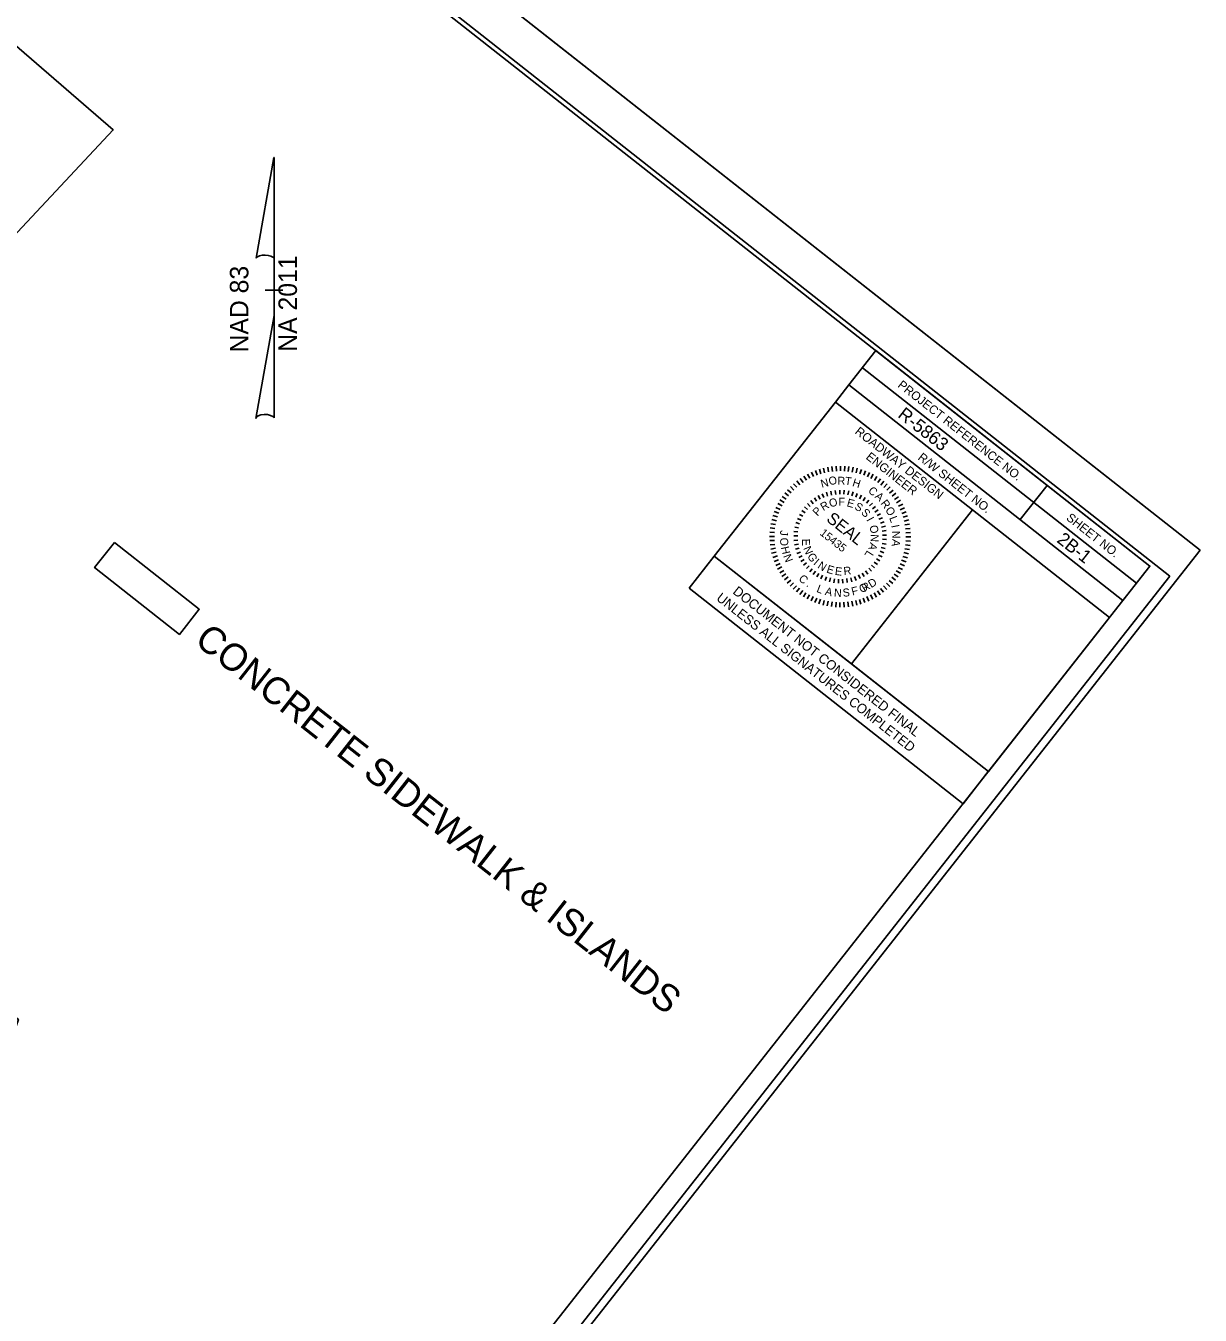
# Model space of a CAD drawing. Extents: x 556999 to 558602, y 505955 to 507732.
# Drawn here: x 558063 to 558602, y 506548 to 507140 of the extents above; entities that cross this region are included whole.
import ezdxf

# ---------------------------------------------------------------- set-up
doc = ezdxf.new("R2010")
doc.units = 0
for name, color, linetype in [('Old_Level_21', 7, 'Continuous'), ('Prop Conc 4in Sidewalk', 7, 'Continuous'), ('Prop Dimension', 7, 'Continuous'), ('Prop Horizontal Alignment Station Label', 7, 'Continuous'), ('Sheet Border Standard 30in CELL', 7, 'Continuous'), ('Sheet Clip Boundary CELL', 7, 'Continuous'), ('Sheet Cutting Line CELL', 7, 'Continuous'), ('Sheet Data Field CELL', 7, 'Continuous'), ('Sheet Plot Border Inside CELL', 7, 'Continuous'), ('Sheet Plot Border Outside CELL', 7, 'Continuous'), ('Sheet Sticker Exception Certification CELL', 7, 'Continuous')]:
    doc.layers.add(name, color=color, linetype=linetype)

msp = doc.modelspace()

# ---------------------------------------------------------------- linework, layer by layer
at = {"layer": 'Old_Level_21'}
for p, q in [((558420.11, 506932.76), (558421.25, 506930.86)), ((558421.82, 506933.71), (558422.84, 506931.76)), ((558423.58, 506934.57), (558424.48, 506932.55)), ((558425.39, 506935.31), (558426.17, 506933.24)), ((558427.24, 506935.94), (558427.89, 506933.83)), ((558429.13, 506936.46), (558429.65, 506934.32)), ((558431.04, 506936.86), (558431.43, 506934.69)), ((558432.98, 506937.15), (558433.24, 506934.96)), ((558434.92, 506937.32), (558435.05, 506935.12)), ((558436.88, 506937.37), (558436.87, 506935.17)), ((558438.84, 506937.31), (558438.7, 506935.11)), ((558440.78, 506937.13), (558440.51, 506934.94)), ((558442.72, 506936.83), (558442.31, 506934.66)), ((558444.63, 506936.41), (558444.09, 506934.27)), ((558446.51, 506935.88), (558445.85, 506933.77)), ((558448.36, 506935.24), (558447.57, 506933.17)), ((558450.16, 506934.48), (558449.25, 506932.47)), ((558451.92, 506933.62), (558450.89, 506931.67)), ((558453.62, 506932.65), (558452.47, 506930.77)), ((558413.95, 506927.96), (558415.51, 506926.4)), ((558415.38, 506929.3), (558416.84, 506927.65)), ((558416.89, 506930.55), (558418.24, 506928.81)), ((558418.47, 506931.71), (558419.72, 506929.88)), ((558455.26, 506931.58), (558454, 506929.77)), ((558456.83, 506930.42), (558455.46, 506928.69)), ((558458.33, 506929.16), (558456.86, 506927.51)), ((558459.75, 506927.82), (558458.19, 506926.26)), ((558409.12, 506921.83), (558411, 506920.69)), ((558410.19, 506923.47), (558412, 506922.21)), ((558411.35, 506925.05), (558413.08, 506923.68)), ((558412.61, 506926.54), (558414.26, 506925.08)), ((558423.27, 506921.51), (558424.43, 506920.09)), ((558424.92, 506922.74), (558425.95, 506921.21)), ((558426.69, 506923.8), (558427.56, 506922.18)), ((558428.56, 506924.69), (558429.26, 506922.99)), ((558430.49, 506925.39), (558431.03, 506923.63)), ((558432.49, 506925.9), (558432.86, 506924.1)), ((558434.53, 506926.22), (558434.72, 506924.38)), ((558436.59, 506926.34), (558436.6, 506924.49)), ((558438.65, 506926.25), (558438.48, 506924.42)), ((558440.69, 506925.97), (558440.35, 506924.17)), ((558442.7, 506925.5), (558442.19, 506923.73)), ((558444.65, 506924.83), (558443.97, 506923.12)), ((558446.53, 506923.98), (558445.69, 506922.34)), ((558448.31, 506922.95), (558447.32, 506921.4)), ((558449.99, 506921.75), (558448.86, 506920.31)), ((558448.86, 506920.31), (558449.99, 506921.75)), ((558461.09, 506926.39), (558459.43, 506924.93)), ((558462.33, 506924.88), (558460.59, 506923.53)), ((558463.49, 506923.3), (558461.67, 506922.05)), ((558464.54, 506921.66), (558462.65, 506920.52)), ((558406.53, 506916.57), (558408.6, 506915.78)), ((558407.29, 506918.38), (558409.3, 506917.46)), ((558408.15, 506920.13), (558410.1, 506919.1)), ((558418.03, 506915.2), (558419.65, 506914.32)), ((558419.1, 506916.96), (558420.63, 506915.93)), ((558420.34, 506918.61), (558421.76, 506917.44)), ((558421.73, 506920.13), (558423.03, 506918.83)), ((558451.55, 506920.39), (558450.28, 506919.07)), ((558452.97, 506918.9), (558451.57, 506917.7)), ((558454.23, 506917.27), (558452.73, 506916.21)), ((558455.34, 506915.53), (558453.74, 506914.62)), ((558465.5, 506919.95), (558463.54, 506918.93)), ((558466.35, 506918.19), (558464.33, 506917.29)), ((558467.09, 506916.38), (558465.03, 506915.6)), ((558404.64, 506909), (558406.83, 506908.73)), ((558404.94, 506910.93), (558407.11, 506910.53)), ((558405.36, 506912.84), (558407.5, 506912.31)), ((558405.89, 506914.73), (558408, 506914.06)), ((558415.9, 506909.41), (558417.7, 506909.03)), ((558416.42, 506911.41), (558418.17, 506910.85)), ((558417.13, 506913.34), (558418.82, 506912.62)), ((558456.27, 506913.69), (558454.59, 506912.94)), ((558457.02, 506911.77), (558455.27, 506911.18)), ((558457.58, 506909.78), (558455.78, 506909.37)), ((558467.73, 506914.53), (558465.62, 506913.88)), ((558468.24, 506912.64), (558466.1, 506912.12)), ((558468.65, 506910.73), (558466.48, 506910.34)), ((558404.39, 506905.1), (558406.6, 506905.09)), ((558404.45, 506903.14), (558406.65, 506903.27)), ((558404.46, 506907.05), (558406.66, 506906.91)), ((558415.43, 506905.32), (558417.28, 506905.29)), ((558415.51, 506903.26), (558417.34, 506903.41)), ((558415.57, 506907.38), (558417.39, 506907.17)), ((558457.94, 506907.75), (558456.11, 506907.51)), ((558458.08, 506903.64), (558456.24, 506903.75)), ((558458.11, 506905.7), (558456.27, 506905.64)), ((558468.94, 506908.79), (558466.74, 506908.53)), ((558469.09, 506902.93), (558466.89, 506903.07)), ((558469.11, 506906.84), (558466.9, 506906.72)), ((558469.16, 506904.89), (558466.95, 506904.89)), ((558404.62, 506901.19), (558406.81, 506901.45)), ((558404.91, 506899.26), (558407.08, 506899.65)), ((558405.31, 506897.34), (558407.45, 506897.86)), ((558415.77, 506901.21), (558417.58, 506901.54)), ((558416.23, 506899.2), (558418, 506899.7)), ((558416.89, 506897.25), (558418.6, 506897.92)), ((558456.8, 506897.6), (558455.07, 506898.24)), ((558457.42, 506899.57), (558455.64, 506900.03)), ((558457.85, 506901.59), (558456.03, 506901.88)), ((558468.19, 506897.14), (558466.05, 506897.68)), ((558468.61, 506899.05), (558466.44, 506899.46)), ((558468.91, 506900.99), (558466.72, 506901.26)), ((558405.83, 506895.46), (558407.94, 506896.11)), ((558406.46, 506893.61), (558408.53, 506894.38)), ((558407.2, 506891.8), (558409.22, 506892.7)), ((558417.73, 506895.36), (558419.37, 506896.19)), ((558418.75, 506893.57), (558420.3, 506894.55)), ((558421.38, 506893.02), (558419.92, 506891.89)), ((558421.28, 506890.32), (558422.61, 506891.58)), ((558452.53, 506890.6), (558451.18, 506891.83)), ((558453.85, 506892.18), (558452.38, 506893.29)), ((558455.01, 506893.89), (558453.44, 506894.85)), ((558455.99, 506895.7), (558454.34, 506896.5)), ((558466.26, 506891.6), (558464.26, 506892.52)), ((558467.02, 506893.41), (558464.96, 506894.2)), ((558467.66, 506895.26), (558465.56, 506895.92)), ((558408.06, 506890.04), (558410.01, 506891.06)), ((558409.01, 506888.33), (558410.9, 506889.46)), ((558410.06, 506886.68), (558411.89, 506887.93)), ((558411.22, 506885.1), (558412.96, 506886.46)), ((558422.77, 506888.89), (558423.97, 506890.28)), ((558424.38, 506887.61), (558425.45, 506889.11)), ((558426.12, 506886.5), (558427.04, 506888.09)), ((558427.95, 506885.56), (558428.71, 506887.24)), ((558429.87, 506884.8), (558430.47, 506886.54)), ((558431.85, 506884.23), (558432.28, 506886.02)), ((558433.88, 506883.85), (558434.13, 506885.67)), ((558435.94, 506883.67), (558436.01, 506885.5)), ((558438, 506883.68), (558437.89, 506885.52)), ((558440.05, 506883.9), (558439.77, 506885.72)), ((558442.07, 506884.31), (558441.61, 506886.1)), ((558444.04, 506884.92), (558443.41, 506886.65)), ((558445.94, 506885.72), (558445.15, 506887.38)), ((558447.76, 506886.69), (558446.81, 506888.27)), ((558449.47, 506887.83), (558448.38, 506889.31)), ((558449.89, 506890.55), (558451.12, 506889.19)), ((558462.2, 506884.94), (558460.47, 506886.31)), ((558463.37, 506886.51), (558461.56, 506887.77)), ((558464.43, 506888.15), (558462.55, 506889.3)), ((558465.4, 506889.85), (558463.45, 506890.88)), ((558412.47, 506883.6), (558414.12, 506885.05)), ((558413.81, 506882.17), (558415.37, 506883.72)), ((558415.22, 506880.82), (558416.69, 506882.47)), ((558416.72, 506879.57), (558418.09, 506881.3)), ((558418.3, 506878.4), (558419.56, 506880.21)), ((558455.09, 506878.28), (558453.84, 506880.1)), ((558456.67, 506879.44), (558455.31, 506881.18)), ((558458.17, 506880.68), (558456.72, 506882.34)), ((558459.6, 506882.02), (558458.05, 506883.58)), ((558460.95, 506883.44), (558459.3, 506884.91)), ((558419.94, 506877.33), (558421.08, 506879.22)), ((558421.63, 506876.37), (558422.67, 506878.32)), ((558423.39, 506875.5), (558424.3, 506877.51)), ((558425.2, 506874.75), (558425.99, 506876.81)), ((558427.04, 506874.11), (558427.71, 506876.21)), ((558428.93, 506873.58), (558429.46, 506875.72)), ((558430.84, 506873.16), (558431.24, 506875.33)), ((558432.77, 506872.86), (558433.04, 506875.05)), ((558434.72, 506872.67), (558434.86, 506874.88)), ((558436.67, 506872.61), (558436.68, 506874.82)), ((558438.63, 506872.66), (558438.5, 506874.86)), ((558440.58, 506872.83), (558440.32, 506875.02)), ((558442.51, 506873.12), (558442.12, 506875.29)), ((558444.43, 506873.53), (558443.9, 506875.67)), ((558446.31, 506874.04), (558445.66, 506876.15)), ((558448.16, 506874.67), (558447.39, 506876.74)), ((558449.97, 506875.42), (558449.07, 506877.44)), ((558451.73, 506876.27), (558450.71, 506878.23)), ((558453.44, 506877.22), (558452.31, 506879.12))]:
    msp.add_line(p, q, dxfattribs=at)
at = {"layer": 'Prop Conc 4in Sidewalk'}
msp.add_lwpolyline([(558103.56, 506902.29), (558142.53, 506871.65), (558133.46, 506860.12), (558094.5, 506890.76)], close=True, dxfattribs=at)
at = {"layer": 'Prop Horizontal Alignment Station Label'}
for p, q in [((558168.62, 507032.79), (558176.82, 507079.14)), ((558176.87, 507079.14), (558176.82, 507079.14)), ((558176.87, 507079.14), (558176.82, 507079.14)), ((558176.87, 507079.14), (558176.87, 507031.34)), ((558176.87, 507006.54), (558176.87, 507032.74)), ((558176.87, 507031.34), (558176.87, 507032.69)), ((558172.87, 507018.14), (558172.82, 507018.14)), ((558176.42, 507018.14), (558172.87, 507018.14)), ((558172.92, 507018.14), (558180.92, 507018.14)), ((558176.87, 507006.54), (558168.52, 506959.29)), ((558176.92, 506959.49), (558176.87, 507006.54))]:
    msp.add_line(p, q, dxfattribs=at)
for centre, start_param, end_param in [((558172.75, 507032.3), 0.216388, 2.908219), ((558172.75, 506959.13), 0.201328, 3.141593)]:
    msp.add_ellipse(centre, major_axis=(4.23, -0.03), ratio=0.461098, start_param=start_param, end_param=end_param, dxfattribs=at)
at = {"layer": 'Sheet Border Standard 30in CELL'}
for p, q in [((558447, 506982.52), (558572.8, 506883.59)), ((558440.81, 506974.66), (558434.63, 506966.8)), ((558440.81, 506974.66), (558566.61, 506875.73)), ((558440.81, 506974.66), (558566.61, 506875.73)), ((558531.81, 506928.54), (558519.45, 506912.82)), ((558497.55, 506917.32), (558441.94, 506846.61))]:
    msp.add_line(p, q, dxfattribs=at)
for points in [[(558579, 506891.48), (557635.74, 507633.27), (557116.49, 506972.99), (558059.75, 506231.2)], [(558453.2, 506990.41), (558579, 506891.48), (558566.61, 506875.73), (558440.81, 506974.66)], [(558434.63, 506966.8), (558497.55, 506917.32), (558441.91, 506846.58), (558379, 506896.06)], [(558497.55, 506917.32), (558560.43, 506867.87), (558504.8, 506797.12), (558441.91, 506846.58)]]:
    msp.add_lwpolyline(points, close=True, dxfattribs=at)
at = {"layer": 'Sheet Clip Boundary CELL'}
msp.add_lwpolyline([(557670.21, 507466.23), (558103.06, 507091.75), (558010.57, 506993.11), (557957.23, 506919.09), (557959.37, 506915.73), (557924.17, 506870.66), (557915.94, 506859.67), (557912.12, 506855.15), (557904.86, 506850.09), (557999.91, 506755.83), (557999.91, 506730.4), (558059.53, 506683.35), (558020.52, 506574.13), (557937.44, 506547.76), (557803.43, 506617.09), (557672.55, 506724.62), (557610.32, 506776.93), (557401.38, 506939.59), (557410.24, 506997.06), (557374.28, 507190.56)], close=True, dxfattribs=at)
at = {"layer": 'Sheet Cutting Line CELL'}
msp.add_line((558602.06, 506898.8), (557543.09, 507731.58), dxfattribs=at)
at = {"layer": 'Sheet Plot Border Inside CELL'}
msp.add_lwpolyline([(558588.12, 506886.9), (557540.16, 507711.03), (557018.38, 507047.54), (558066.35, 506223.41)], close=True, dxfattribs=at)
at = {"layer": 'Sheet Plot Border Outside CELL'}
msp.add_lwpolyline([(558602.06, 506898.8), (557543.09, 507731.58), (556999.11, 507039.85), (558058.08, 506207.07)], close=True, dxfattribs=at)
at = {"layer": 'Sheet Sticker Exception Certification CELL'}
for p, q in [((558367.38, 506881.28), (558379, 506896.06)), ((558379, 506896.06), (558504.79, 506797.13)), ((558493.17, 506782.35), (558367.38, 506881.28)), ((558504.78, 506797.12), (558493.16, 506782.35))]:
    msp.add_line(p, q, dxfattribs=at)

# ---------------------------------------------------------------- texts
at = {"layer": 'Old_Level_21'}
for s, height, rotation, p in [('O', 3.68, 13.4556, (558431.94, 506928.49)), ('N', 3.68, 15.41503, (558428.36, 506927.36)), ('R', 3.68, 0.39887, (558435.57, 506928.79)), ('T', 3.68, 352.23791, (558438.78, 506928.87)), ('H', 3.68, 342.80596, (558442.1, 506928.3)), ('C', 3.68, 319.09527, (558449.3, 506925.62)), ('R', 3.68, 30.57141, (558429.02, 506916.67)), ('O', 3.68, 15.27517, (558432.21, 506918.37)), ('F', 3.68, 359.97892, (558435.96, 506919.18)), ('E', 3.68, 344.68268, (558439.56, 506918.99)), ('A', 3.68, 319.09527, (558452.41, 506923.08)), ('R', 3.68, 307.08596, (558455.13, 506920.24)), ('P', 3.68, 45.86766, (558426.33, 506914.16)), ('SEAL', 5.518, 321.73831, (558430.04, 506912.41)), ('S', 3.68, 329.38643, (558443.05, 506917.85)), ('S', 3.68, 314.09018, (558446.12, 506915.81)), ('O', 3.68, 304.02915, (558457.27, 506917.2)), ('I', 3.68, 298.79394, (558448.7, 506912.77)), ('O', 3.68, 283.49769, (558450.14, 506909.81)), ('L', 3.68, 290.89287, (558459.2, 506913.6)), ('I', 3.68, 281.3174, (558460.2, 506910.09)), ('J', 3.68, 265.67332, (558409.29, 506907.98)), ('O', 3.68, 273.74514, (558409.13, 506904.38)), ('E', 3.68, 271.8084, (558419.2, 506903.98)), ('15435', 3.676, 321.73831, (558427.15, 506906.08)), ('N', 3.68, 268.20145, (558450.84, 506906.12)), ('A', 3.68, 262.2554, (558460.8, 506903.96)), ('N', 3.68, 272.02293, (558460.58, 506907.59)), ('H', 3.68, 282.38789, (558409.56, 506900.09)), ('N', 3.68, 292.66347, (558419.73, 506899.67)), ('G', 3.68, 301.4297, (558421.49, 506896.08)), ('L', 3.68, 237.60895, (558449.24, 506898.92)), ('A', 3.68, 252.9052, (558450.56, 506902.51)), ('N', 3.68, 291.06047, (558410.58, 506896.12)), ('I', 3.68, 319.5245, (558424.2, 506892.45)), ('N', 3.68, 327.15416, (558426.08, 506890.81)), ('E', 3.68, 342.54623, (558430.24, 506888.57)), ('R', 3.68, 6.3032, (558438.51, 506887.31)), ('C', 3.68, 317.82826, (558417.39, 506885.27)), ('E', 3.68, 352.53211, (558434.18, 506887.47)), (' RD', 3.676, 31.41073, (558446.79, 506878.74)), ('.', 3.68, 325.57061, (558420.92, 506882.37)), ('L', 3.68, 338.35492, (558425.62, 506879.7)), ('A', 3.68, 347.35749, (558429.57, 506878.29)), ('N', 3.68, 356.1801, (558433.81, 506877.5)), ('S', 3.68, 5.06273, (558438.09, 506877.37)), ('F', 3.68, 13.94536, (558442.42, 506877.93)), ('O ', 3.676, 22.73797, (558446.36, 506879.05))]:
    msp.add_text(s, height=height, rotation=rotation, dxfattribs=at).set_placement(p)
at = {"layer": 'Prop Dimension'}
msp.add_text('CONCRETE SIDEWALK & ISLANDS', height=12.5, rotation=321.81814, dxfattribs=at).set_placement((558139.8, 506856.21))
at = {"layer": 'Prop Horizontal Alignment Station Label'}
for s, p in [('NA 2011', (558187.39, 506989.87)), ('NAD 83', (558165.1, 506989.53))]:
    msp.add_text(s, height=8.5, rotation=90, dxfattribs=at).set_placement(p)
at = {"layer": 'Sheet Border Standard 30in CELL'}
for s, height, p in [('PROJECT REFERENCE NO.', 4.0001, (558462.86, 506973.96)), ('ROADWAY DESIGN', 4.0001, (558443.22, 506952.62)), ('ENGINEER', 4, (558448.26, 506940.97)), ('R/W SHEET NO.', 4.0001, (558472.11, 506940.69)), ('SHEET NO.', 4, (558540.25, 506913))]:
    msp.add_text(s, height=height, rotation=321.81814, dxfattribs=at).set_placement(p)
at = {"layer": 'Sheet Data Field CELL'}
for s, p in [('R-5863   ', (558462.81, 506960.16)), ('2B-1 ', (558535.84, 506902.78))]:
    msp.add_text(s, height=6, rotation=321.81814, dxfattribs=at).set_placement(p)
at = {"layer": 'Sheet Sticker Exception Certification CELL'}
for s, p in [('DOCUMENT NOT CONSIDERED FINAL', (558387.13, 506879.13)), ('UNLESS ALL SIGNATURES COMPLETED', (558379.59, 506876.1))]:
    msp.add_text(s, height=4.4, rotation=321.81814, dxfattribs=at).set_placement(p)

doc.saveas('drawing.dxf')
